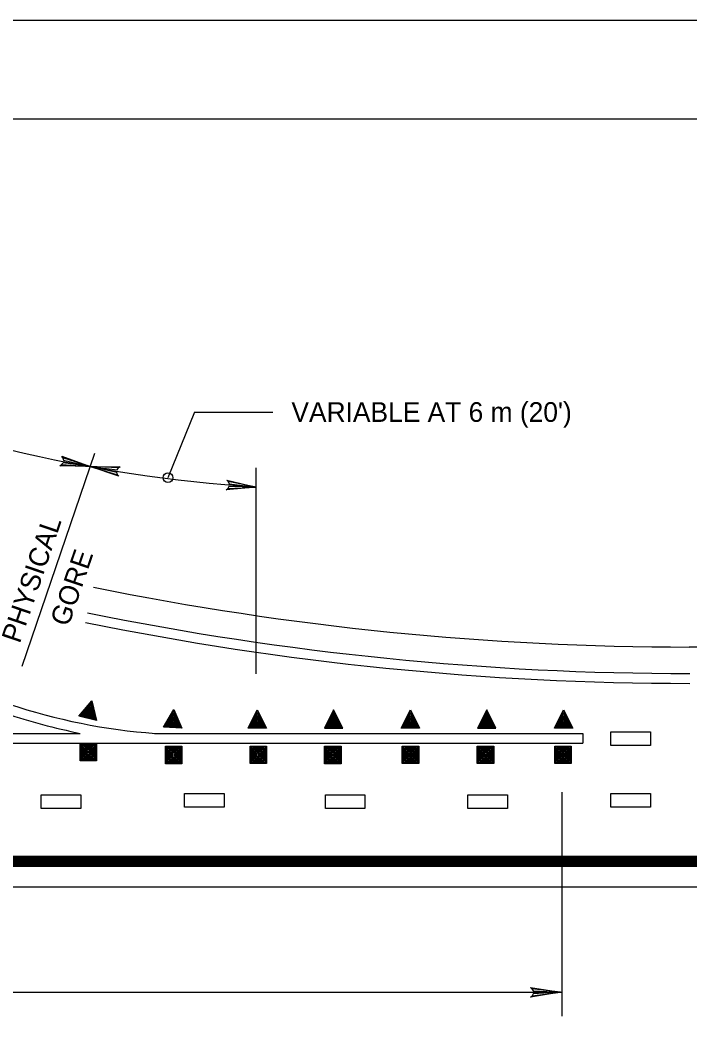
# Model space of a CAD drawing. Extents: x 639362 to 641108, y 298458 to 299646.
# Drawn here: x 639652.3 to 639754.2, y 299491.1 to 299645.6 of the extents above; entities that cross this region are included whole.
import ezdxf

# ---------------------------------------------------------------- set-up
doc = ezdxf.new("R2010")
doc.units = 0
for name, color, linetype in [('1', 7, 'Continuous'), ('2', 7, 'Continuous'), ('PLT-BNDY', 7, 'Continuous')]:
    doc.layers.add(name, color=color, linetype=linetype)

msp = doc.modelspace()

# ---------------------------------------------------------------- linework, layer by layer
at = {"layer": '1'}
msp.add_line((639402.31, 299630.63), (640188.31, 299630.63), dxfattribs=at)
at = {"layer": '2'}
for p, q in [((639678.76, 299585.99), (639674.74, 299576)), ((639678.76, 299585.99), (639690.69, 299585.99)), ((639663.56, 299579.69), (639652.5, 299547.26)), ((639688.17, 299546.13), (639688.17, 299577.52)), ((639813.29, 299550.23), (639754.09, 299550.23)), ((639661.15, 299539.71), (639663.17, 299542.06)), ((639661.33, 299539.76), (639663.12, 299541.85)), ((639661.51, 299539.82), (639663.06, 299541.63)), ((639661.69, 299539.88), (639663.01, 299541.42)), ((639661.87, 299539.93), (639662.96, 299541.2)), ((639662.96, 299541.2), (639663.32, 299539.57)), ((639663.01, 299541.42), (639663.45, 299539.44)), ((639663.06, 299541.63), (639663.58, 299539.31)), ((639663.12, 299541.85), (639663.71, 299539.17)), ((639663.17, 299542.06), (639663.84, 299539.03)), ((639663.84, 299539.03), (639661.15, 299539.71)), ((639663.71, 299539.17), (639661.33, 299539.76)), ((639663.58, 299539.31), (639661.51, 299539.82)), ((639663.45, 299539.44), (639661.69, 299539.88)), ((639663.32, 299539.57), (639661.87, 299539.93)), ((639662.05, 299540), (639662.9, 299540.99)), ((639663.19, 299539.71), (639662.05, 299540)), ((639662.23, 299540.05), (639662.85, 299540.78)), ((639663.06, 299539.84), (639662.23, 299540.05)), ((639662.41, 299540.11), (639662.79, 299540.56)), ((639662.93, 299539.98), (639662.41, 299540.11)), ((639662.58, 299540.17), (639662.74, 299540.35)), ((639662.79, 299540.11), (639662.58, 299540.17)), ((639662.74, 299540.35), (639662.79, 299540.11)), ((639662.79, 299540.56), (639662.93, 299539.98)), ((639662.85, 299540.78), (639663.06, 299539.84)), ((639662.9, 299540.99), (639663.19, 299539.71)), ((639674.08, 299538.03), (639675.61, 299540.73)), ((639674.24, 299538.12), (639675.59, 299540.5)), ((639674.41, 299538.21), (639675.58, 299540.28)), ((639674.57, 299538.3), (639675.57, 299540.06)), ((639674.74, 299538.39), (639675.56, 299539.84)), ((639674.9, 299538.48), (639675.55, 299539.62)), ((639675.55, 299539.62), (639676.08, 299538.42)), ((639675.56, 299539.84), (639676.23, 299538.31)), ((639675.57, 299540.06), (639676.39, 299538.2)), ((639675.58, 299540.28), (639676.53, 299538.09)), ((639675.59, 299540.5), (639676.69, 299537.99)), ((639675.61, 299540.73), (639676.85, 299537.88)), ((639686.95, 299537.88), (639688.34, 299540.65)), ((639687.11, 299537.98), (639688.34, 299540.43)), ((639687.27, 299538.08), (639688.34, 299540.21)), ((639687.43, 299538.18), (639688.34, 299539.99)), ((639687.59, 299538.28), (639688.34, 299539.77)), ((639687.75, 299538.38), (639688.34, 299539.55)), ((639688.34, 299540.65), (639689.73, 299537.88)), ((639688.34, 299540.43), (639689.57, 299537.98)), ((639688.34, 299540.21), (639689.41, 299538.08)), ((639688.34, 299539.99), (639689.25, 299538.18)), ((639688.34, 299539.77), (639689.09, 299538.27)), ((639688.34, 299539.55), (639688.93, 299538.37)), ((639699.96, 299540.65), (639698.57, 299537.88)), ((639699.95, 299540.43), (639698.73, 299537.98)), ((639699.96, 299540.21), (639698.89, 299538.08)), ((639699.95, 299539.99), (639699.05, 299538.18)), ((639699.95, 299539.77), (639699.21, 299538.27)), ((639699.96, 299539.55), (639699.37, 299538.37)), ((639701.18, 299537.98), (639699.95, 299540.43)), ((639700.86, 299538.18), (639699.95, 299539.99)), ((639700.7, 299538.28), (639699.95, 299539.77)), ((639701.34, 299537.88), (639699.96, 299540.65)), ((639701.02, 299538.08), (639699.96, 299540.21)), ((639700.54, 299538.38), (639699.96, 299539.55)), ((639710.26, 299537.88), (639711.65, 299540.65)), ((639710.42, 299537.98), (639711.65, 299540.43)), ((639710.58, 299538.08), (639711.65, 299540.21)), ((639710.74, 299538.18), (639711.65, 299539.99)), ((639710.9, 299538.28), (639711.66, 299539.77)), ((639711.06, 299538.38), (639711.65, 299539.55)), ((639711.65, 299540.65), (639713.04, 299537.88)), ((639711.65, 299540.43), (639712.88, 299537.98)), ((639711.65, 299540.21), (639712.72, 299538.08)), ((639711.65, 299539.99), (639712.56, 299538.18)), ((639711.65, 299539.55), (639712.24, 299538.37)), ((639711.66, 299539.77), (639712.4, 299538.27)), ((639723.27, 299540.65), (639721.88, 299537.88)), ((639723.27, 299540.43), (639722.04, 299537.98)), ((639723.27, 299540.21), (639722.2, 299538.08)), ((639723.27, 299539.99), (639722.36, 299538.18)), ((639723.26, 299539.77), (639722.52, 299538.27)), ((639723.27, 299539.55), (639722.68, 299538.37)), ((639724.01, 299538.28), (639723.26, 299539.77)), ((639724.65, 299537.88), (639723.27, 299540.65)), ((639724.49, 299537.98), (639723.27, 299540.43)), ((639724.33, 299538.08), (639723.27, 299540.21)), ((639724.17, 299538.18), (639723.27, 299539.99)), ((639723.85, 299538.38), (639723.27, 299539.55)), ((639733.57, 299537.88), (639734.96, 299540.65)), ((639733.73, 299537.98), (639734.96, 299540.43)), ((639733.9, 299538.08), (639734.96, 299540.21)), ((639734.06, 299538.18), (639734.96, 299539.99)), ((639734.22, 299538.28), (639734.97, 299539.77)), ((639734.38, 299538.38), (639734.96, 299539.55)), ((639734.96, 299540.65), (639736.35, 299537.88)), ((639734.96, 299540.43), (639736.19, 299537.98)), ((639734.96, 299540.21), (639736.03, 299538.08)), ((639734.96, 299539.99), (639735.87, 299538.18)), ((639734.96, 299539.55), (639735.55, 299538.37)), ((639734.97, 299539.77), (639735.71, 299538.27)), ((639676.85, 299537.88), (639674.08, 299538.03)), ((639676.69, 299537.99), (639674.24, 299538.12)), ((639676.53, 299538.09), (639674.41, 299538.21)), ((639676.39, 299538.2), (639674.57, 299538.3)), ((639676.23, 299538.31), (639674.74, 299538.39)), ((639676.08, 299538.42), (639674.9, 299538.48)), ((639675.06, 299538.57), (639675.54, 299539.4)), ((639675.92, 299538.53), (639675.06, 299538.57)), ((639675.22, 299538.66), (639675.53, 299539.18)), ((639675.76, 299538.63), (639675.22, 299538.66)), ((639675.39, 299538.75), (639675.51, 299538.96)), ((639675.61, 299538.74), (639675.39, 299538.75)), ((639675.51, 299538.96), (639675.61, 299538.74)), ((639675.53, 299539.18), (639675.76, 299538.63)), ((639675.54, 299539.4), (639675.92, 299538.53)), ((639689.57, 299537.98), (639687.11, 299537.98)), ((639689.41, 299538.08), (639687.27, 299538.08)), ((639689.25, 299538.18), (639687.43, 299538.18)), ((639689.09, 299538.27), (639687.59, 299538.28)), ((639688.93, 299538.37), (639687.75, 299538.38)), ((639687.91, 299538.47), (639688.34, 299539.33)), ((639688.77, 299538.47), (639687.91, 299538.47)), ((639688.07, 299538.58), (639688.34, 299539.1)), ((639688.61, 299538.57), (639688.07, 299538.58)), ((639688.23, 299538.67), (639688.34, 299538.88)), ((639688.45, 299538.67), (639688.23, 299538.67)), ((639688.34, 299539.33), (639688.77, 299538.47)), ((639688.34, 299539.1), (639688.61, 299538.57)), ((639688.34, 299538.88), (639688.45, 299538.67)), ((639698.73, 299537.98), (639701.18, 299537.98)), ((639698.89, 299538.08), (639701.02, 299538.08)), ((639699.05, 299538.18), (639700.86, 299538.18)), ((639699.21, 299538.27), (639700.7, 299538.28)), ((639699.37, 299538.37), (639700.54, 299538.38)), ((639699.95, 299539.33), (639699.53, 299538.47)), ((639699.53, 299538.47), (639700.38, 299538.47)), ((639699.96, 299539.1), (639699.69, 299538.57)), ((639699.69, 299538.57), (639700.23, 299538.58)), ((639699.96, 299538.88), (639699.85, 299538.67)), ((639699.85, 299538.67), (639700.07, 299538.67)), ((639700.38, 299538.47), (639699.95, 299539.33)), ((639700.23, 299538.58), (639699.96, 299539.1)), ((639700.07, 299538.67), (639699.96, 299538.88)), ((639712.88, 299537.98), (639710.42, 299537.98)), ((639712.72, 299538.08), (639710.58, 299538.08)), ((639712.56, 299538.18), (639710.74, 299538.18)), ((639712.4, 299538.27), (639710.9, 299538.28)), ((639712.24, 299538.37), (639711.06, 299538.38)), ((639711.22, 299538.47), (639711.65, 299539.33)), ((639712.08, 299538.47), (639711.22, 299538.47)), ((639711.38, 299538.58), (639711.65, 299539.1)), ((639711.92, 299538.57), (639711.38, 299538.58)), ((639711.54, 299538.67), (639711.65, 299538.88)), ((639711.76, 299538.67), (639711.54, 299538.67)), ((639711.65, 299539.33), (639712.08, 299538.47)), ((639711.65, 299539.1), (639711.92, 299538.57)), ((639711.65, 299538.88), (639711.76, 299538.67)), ((639722.04, 299537.98), (639724.49, 299537.98)), ((639722.2, 299538.08), (639724.33, 299538.08)), ((639722.36, 299538.18), (639724.17, 299538.18)), ((639722.52, 299538.27), (639724.01, 299538.28)), ((639722.68, 299538.37), (639723.85, 299538.38)), ((639723.27, 299539.33), (639722.84, 299538.47)), ((639722.84, 299538.47), (639723.69, 299538.47)), ((639723.27, 299539.1), (639723, 299538.57)), ((639723, 299538.57), (639723.54, 299538.58)), ((639723.27, 299538.88), (639723.16, 299538.67)), ((639723.16, 299538.67), (639723.38, 299538.67)), ((639723.69, 299538.47), (639723.27, 299539.33)), ((639723.54, 299538.58), (639723.27, 299539.1)), ((639723.38, 299538.67), (639723.27, 299538.88)), ((639736.19, 299537.98), (639733.73, 299537.98)), ((639736.03, 299538.08), (639733.9, 299538.08)), ((639735.87, 299538.18), (639734.06, 299538.18)), ((639735.71, 299538.27), (639734.22, 299538.28)), ((639735.55, 299538.37), (639734.38, 299538.38)), ((639734.54, 299538.47), (639734.96, 299539.33)), ((639735.39, 299538.47), (639734.54, 299538.47)), ((639734.69, 299538.58), (639734.96, 299539.1)), ((639735.23, 299538.57), (639734.69, 299538.58)), ((639734.85, 299538.67), (639734.96, 299538.88)), ((639735.07, 299538.67), (639734.85, 299538.67)), ((639734.96, 299539.33), (639735.39, 299538.47)), ((639734.96, 299539.1), (639735.23, 299538.57)), ((639734.96, 299538.88), (639735.07, 299538.67)), ((639512.29, 299537.09), (639661.38, 299537.09)), ((639672.69, 299537.09), (639737.89, 299537.09)), ((639689.73, 299537.88), (639686.95, 299537.88)), ((639698.57, 299537.88), (639701.34, 299537.88)), ((639713.04, 299537.88), (639710.26, 299537.88)), ((639721.88, 299537.88), (639724.65, 299537.88)), ((639736.35, 299537.88), (639733.57, 299537.88)), ((639737.89, 299537.09), (639737.89, 299535.59)), ((639742.17, 299535.25), (639742.17, 299537.32)), ((639742.18, 299537.32), (639748.19, 299537.32)), ((639748.19, 299537.32), (639748.19, 299535.25)), ((639512.29, 299535.59), (639737.89, 299535.59)), ((639661.36, 299535.58), (639663.86, 299535.58)), ((639661.36, 299532.92), (639661.36, 299535.58)), ((639661.55, 299535.44), (639663.68, 299535.44)), ((639661.55, 299533.05), (639661.55, 299535.44)), ((639661.73, 299535.27), (639663.5, 299535.27)), ((639661.73, 299533.23), (639661.73, 299535.27)), ((639661.9, 299535.09), (639663.32, 299535.09)), ((639661.9, 299533.41), (639661.9, 299535.09)), ((639662.08, 299534.91), (639663.15, 299534.91)), ((639662.08, 299533.58), (639662.08, 299534.91)), ((639663.15, 299534.91), (639663.15, 299533.58)), ((639663.32, 299535.09), (639663.32, 299533.41)), ((639663.5, 299535.27), (639663.5, 299533.23)), ((639663.68, 299535.44), (639663.68, 299533.05)), ((639663.86, 299535.58), (639663.86, 299532.92)), ((639674.36, 299535.12), (639676.86, 299535.12)), ((639674.36, 299532.47), (639674.36, 299535.12)), ((639674.55, 299534.99), (639676.68, 299534.99)), ((639674.55, 299532.59), (639674.55, 299534.99)), ((639676.68, 299534.99), (639676.68, 299532.59)), ((639676.86, 299535.12), (639676.86, 299532.47)), ((639687.26, 299535.15), (639689.76, 299535.15)), ((639687.26, 299532.5), (639687.26, 299535.15)), ((639687.44, 299535.02), (639689.57, 299535.02)), ((639687.44, 299532.62), (639687.44, 299535.02)), ((639689.57, 299535.02), (639689.57, 299532.62)), ((639689.76, 299535.15), (639689.76, 299532.5)), ((639698.59, 299535.12), (639701.08, 299535.12)), ((639698.59, 299532.47), (639698.59, 299535.12)), ((639698.77, 299534.99), (639700.9, 299534.99)), ((639698.77, 299532.59), (639698.77, 299534.99)), ((639700.9, 299534.99), (639700.9, 299532.59)), ((639701.08, 299535.12), (639701.08, 299532.47)), ((639710.41, 299535.15), (639712.91, 299535.15)), ((639710.41, 299532.5), (639710.41, 299535.15)), ((639710.6, 299535.02), (639712.73, 299535.02)), ((639710.6, 299532.62), (639710.6, 299535.02)), ((639712.73, 299535.02), (639712.73, 299532.62)), ((639712.91, 299535.15), (639712.91, 299532.5)), ((639721.83, 299535.14), (639724.33, 299535.14)), ((639721.83, 299532.49), (639721.83, 299535.14)), ((639722.01, 299535.01), (639724.14, 299535.01)), ((639722.01, 299532.61), (639722.01, 299535.01)), ((639724.14, 299535.01), (639724.14, 299532.61)), ((639724.33, 299535.14), (639724.33, 299532.49)), ((639733.62, 299535.15), (639736.12, 299535.15)), ((639733.62, 299532.5), (639733.62, 299535.15)), ((639733.81, 299535.02), (639735.93, 299535.02)), ((639733.81, 299532.62), (639733.81, 299535.02)), ((639735.93, 299535.02), (639735.93, 299532.62)), ((639736.12, 299535.15), (639736.12, 299532.5)), ((639748.19, 299535.25), (639742.18, 299535.25)), ((639663.32, 299533.41), (639661.9, 299533.41)), ((639663.15, 299533.58), (639662.08, 299533.58)), ((639662.26, 299533.76), (639662.26, 299534.74)), ((639662.26, 299534.74), (639662.97, 299534.74)), ((639662.97, 299533.76), (639662.26, 299533.76)), ((639662.44, 299534.56), (639662.79, 299534.56)), ((639662.44, 299533.94), (639662.44, 299534.56)), ((639662.79, 299533.94), (639662.44, 299533.94)), ((639662.61, 299534.38), (639662.61, 299534.11)), ((639662.79, 299534.56), (639662.79, 299533.94)), ((639662.97, 299534.74), (639662.97, 299533.76)), ((639674.73, 299534.81), (639676.5, 299534.81)), ((639674.73, 299532.77), (639674.73, 299534.81)), ((639674.9, 299534.63), (639676.32, 299534.63)), ((639674.9, 299532.95), (639674.9, 299534.63)), ((639675.08, 299534.46), (639676.15, 299534.46)), ((639675.08, 299533.13), (639675.08, 299534.46)), ((639675.26, 299533.3), (639675.26, 299534.28)), ((639675.26, 299534.28), (639675.97, 299534.28)), ((639675.44, 299534.1), (639675.79, 299534.1)), ((639675.44, 299533.48), (639675.44, 299534.1)), ((639675.79, 299533.48), (639675.44, 299533.48)), ((639675.61, 299533.92), (639675.61, 299533.66)), ((639675.79, 299534.1), (639675.79, 299533.48)), ((639675.97, 299534.28), (639675.97, 299533.3)), ((639676.15, 299534.46), (639676.15, 299533.13)), ((639676.32, 299534.63), (639676.32, 299532.95)), ((639676.5, 299534.81), (639676.5, 299532.77)), ((639687.62, 299534.84), (639689.4, 299534.84)), ((639687.62, 299532.8), (639687.62, 299534.84)), ((639687.8, 299534.66), (639689.22, 299534.66)), ((639687.8, 299532.98), (639687.8, 299534.66)), ((639687.98, 299534.48), (639689.04, 299534.48)), ((639687.98, 299533.16), (639687.98, 299534.48)), ((639688.16, 299533.33), (639688.16, 299534.31)), ((639688.16, 299534.31), (639688.87, 299534.31)), ((639688.87, 299533.33), (639688.16, 299533.33)), ((639688.33, 299534.13), (639688.69, 299534.13)), ((639688.33, 299533.51), (639688.33, 299534.13)), ((639688.69, 299533.51), (639688.33, 299533.51)), ((639688.51, 299533.95), (639688.51, 299533.69)), ((639688.69, 299534.13), (639688.69, 299533.51)), ((639688.87, 299534.31), (639688.87, 299533.33)), ((639689.04, 299534.48), (639689.04, 299533.16)), ((639689.22, 299534.66), (639689.22, 299532.98)), ((639689.4, 299534.84), (639689.4, 299532.8)), ((639698.95, 299534.81), (639700.72, 299534.81)), ((639698.95, 299532.77), (639698.95, 299534.81)), ((639699.13, 299534.63), (639700.55, 299534.63)), ((639699.13, 299532.95), (639699.13, 299534.63)), ((639699.3, 299534.46), (639700.37, 299534.46)), ((639699.3, 299533.13), (639699.3, 299534.46)), ((639699.48, 299533.3), (639699.48, 299534.28)), ((639699.48, 299534.28), (639700.19, 299534.28)), ((639699.66, 299534.1), (639700.01, 299534.1)), ((639699.66, 299533.48), (639699.66, 299534.1)), ((639700.01, 299533.48), (639699.66, 299533.48)), ((639699.84, 299533.92), (639699.84, 299533.66)), ((639700.01, 299534.1), (639700.01, 299533.48)), ((639700.19, 299534.28), (639700.19, 299533.3)), ((639700.37, 299534.46), (639700.37, 299533.13)), ((639700.55, 299534.63), (639700.55, 299532.95)), ((639700.72, 299534.81), (639700.72, 299532.77)), ((639710.78, 299534.84), (639712.55, 299534.84)), ((639710.78, 299532.8), (639710.78, 299534.84)), ((639710.95, 299534.66), (639712.37, 299534.66)), ((639710.95, 299532.98), (639710.95, 299534.66)), ((639711.13, 299534.49), (639712.2, 299534.49)), ((639711.13, 299533.16), (639711.13, 299534.49)), ((639711.31, 299533.33), (639711.31, 299534.31)), ((639711.31, 299534.31), (639712.02, 299534.31)), ((639712.02, 299533.33), (639711.31, 299533.33)), ((639711.49, 299534.13), (639711.84, 299534.13)), ((639711.49, 299533.51), (639711.49, 299534.13)), ((639711.84, 299533.51), (639711.49, 299533.51)), ((639711.66, 299533.95), (639711.66, 299533.69)), ((639711.84, 299534.13), (639711.84, 299533.51)), ((639712.02, 299534.31), (639712.02, 299533.33)), ((639712.2, 299534.49), (639712.2, 299533.16)), ((639712.37, 299534.66), (639712.37, 299532.98)), ((639712.55, 299534.84), (639712.55, 299532.8)), ((639722.19, 299534.83), (639723.97, 299534.83)), ((639722.19, 299532.79), (639722.19, 299534.83)), ((639722.37, 299534.65), (639723.79, 299534.65)), ((639722.37, 299532.97), (639722.37, 299534.65)), ((639722.55, 299534.47), (639723.61, 299534.47)), ((639722.55, 299533.15), (639722.55, 299534.47)), ((639722.72, 299533.32), (639722.72, 299534.3)), ((639722.72, 299534.3), (639723.43, 299534.3)), ((639723.43, 299533.32), (639722.72, 299533.32)), ((639722.9, 299534.12), (639723.26, 299534.12)), ((639722.9, 299533.5), (639722.9, 299534.12)), ((639723.26, 299533.5), (639722.9, 299533.5)), ((639723.08, 299533.94), (639723.08, 299533.68)), ((639723.26, 299534.12), (639723.26, 299533.5)), ((639723.43, 299534.3), (639723.43, 299533.32)), ((639723.61, 299534.47), (639723.61, 299533.15)), ((639723.79, 299534.65), (639723.79, 299532.97)), ((639723.97, 299534.83), (639723.97, 299532.79)), ((639733.98, 299534.84), (639735.76, 299534.84)), ((639733.98, 299532.8), (639733.98, 299534.84)), ((639734.16, 299534.66), (639735.58, 299534.66)), ((639734.16, 299532.98), (639734.16, 299534.66)), ((639734.34, 299534.48), (639735.4, 299534.48)), ((639734.34, 299533.16), (639734.34, 299534.48)), ((639734.52, 299533.33), (639734.52, 299534.31)), ((639734.52, 299534.31), (639735.23, 299534.31)), ((639735.23, 299533.33), (639734.52, 299533.33)), ((639734.69, 299534.13), (639735.05, 299534.13)), ((639734.69, 299533.51), (639734.69, 299534.13)), ((639735.05, 299533.51), (639734.69, 299533.51)), ((639734.87, 299533.95), (639734.87, 299533.69)), ((639735.05, 299534.13), (639735.05, 299533.51)), ((639735.23, 299534.31), (639735.23, 299533.33)), ((639735.4, 299534.48), (639735.4, 299533.16)), ((639735.58, 299534.66), (639735.58, 299532.98)), ((639735.76, 299534.84), (639735.76, 299532.8)), ((639663.86, 299532.92), (639661.36, 299532.92)), ((639663.68, 299533.05), (639661.55, 299533.05)), ((639663.5, 299533.23), (639661.73, 299533.23)), ((639676.86, 299532.47), (639674.36, 299532.47)), ((639676.68, 299532.59), (639674.55, 299532.59)), ((639676.5, 299532.77), (639674.73, 299532.77)), ((639676.32, 299532.95), (639674.9, 299532.95)), ((639676.15, 299533.13), (639675.08, 299533.13)), ((639675.97, 299533.3), (639675.26, 299533.3)), ((639689.76, 299532.5), (639687.26, 299532.5)), ((639689.57, 299532.62), (639687.44, 299532.62)), ((639689.4, 299532.8), (639687.62, 299532.8)), ((639689.22, 299532.98), (639687.8, 299532.98)), ((639689.04, 299533.16), (639687.98, 299533.16)), ((639701.08, 299532.47), (639698.59, 299532.47)), ((639700.9, 299532.59), (639698.77, 299532.59)), ((639700.72, 299532.77), (639698.95, 299532.77)), ((639700.55, 299532.95), (639699.13, 299532.95)), ((639700.37, 299533.13), (639699.3, 299533.13)), ((639700.19, 299533.3), (639699.48, 299533.3)), ((639712.91, 299532.5), (639710.41, 299532.5)), ((639712.73, 299532.62), (639710.6, 299532.62)), ((639712.55, 299532.8), (639710.78, 299532.8)), ((639712.37, 299532.98), (639710.95, 299532.98)), ((639712.2, 299533.16), (639711.13, 299533.16)), ((639724.33, 299532.49), (639721.83, 299532.49)), ((639724.14, 299532.61), (639722.01, 299532.61)), ((639723.97, 299532.79), (639722.19, 299532.79)), ((639723.79, 299532.97), (639722.37, 299532.97)), ((639723.61, 299533.15), (639722.55, 299533.15)), ((639736.12, 299532.5), (639733.62, 299532.5)), ((639735.93, 299532.62), (639733.81, 299532.62)), ((639735.76, 299532.8), (639733.98, 299532.8)), ((639735.58, 299532.98), (639734.16, 299532.98)), ((639735.4, 299533.16), (639734.34, 299533.16)), ((639655.45, 299525.67), (639655.45, 299527.74)), ((639655.45, 299527.74), (639661.46, 299527.74)), ((639661.46, 299527.74), (639661.46, 299525.67)), ((639677.26, 299525.86), (639677.26, 299527.93)), ((639677.26, 299527.93), (639683.27, 299527.93)), ((639683.27, 299527.93), (639683.27, 299525.86)), ((639698.71, 299525.67), (639698.71, 299527.74)), ((639698.71, 299527.74), (639704.72, 299527.74)), ((639704.72, 299527.74), (639704.72, 299525.67)), ((639720.41, 299525.67), (639720.41, 299527.74)), ((639720.41, 299527.74), (639726.42, 299527.74)), ((639726.42, 299527.74), (639726.42, 299525.67)), ((639734.72, 299528.16), (639734.72, 299494.02)), ((639742.17, 299525.86), (639742.17, 299527.93)), ((639742.17, 299527.93), (639748.19, 299527.93)), ((639748.19, 299527.93), (639748.19, 299525.86)), ((639661.46, 299525.67), (639655.45, 299525.67)), ((639683.27, 299525.86), (639677.26, 299525.86)), ((639704.72, 299525.67), (639698.71, 299525.67)), ((639726.42, 299525.67), (639720.41, 299525.67)), ((639748.19, 299525.86), (639742.17, 299525.86)), ((639512.29, 299518.38), (639813.29, 299518.38)), ((639512.29, 299518.23), (639813.29, 299518.23)), ((639512.29, 299518.08), (639813.29, 299518.08)), ((639512.29, 299517.93), (639813.29, 299517.93)), ((639512.29, 299517.78), (639813.29, 299517.78)), ((639512.29, 299517.63), (639813.29, 299517.63)), ((639512.29, 299517.48), (639813.29, 299517.48)), ((639512.29, 299517.33), (639813.29, 299517.33)), ((639512.29, 299517.18), (639813.29, 299517.18)), ((639512.29, 299517.03), (639813.29, 299517.03)), ((639512.29, 299516.88), (639813.29, 299516.88)), ((639512.29, 299513.74), (639813.29, 299513.74)), ((639531.37, 299497.67), (639734.72, 299497.67))]:
    msp.add_line(p, q, dxfattribs=at)
for points in [[(639658.74, 299579.03), (639658.84, 299578.69), (639662.88, 299577.69), (639658.74, 299579.03), (639658.56, 299579.26), (639662.88, 299577.69), (639658.76, 299578.26), (639658.55, 299577.99), (639662.88, 299577.69), (639658.28, 299577.83), (639658.55, 299577.99)], [(639667.06, 299576.46), (639666.94, 299576.79), (639662.88, 299577.7), (639667.06, 299576.46), (639667.24, 299576.23), (639662.88, 299577.7), (639667.02, 299577.22), (639667.22, 299577.5), (639662.88, 299577.7), (639667.48, 299577.67), (639667.22, 299577.5)], [(639683.9, 299575.41), (639684.04, 299575.08), (639688.17, 299574.58), (639683.9, 299575.41), (639683.69, 299575.61), (639688.17, 299574.58), (639684.02, 299574.65), (639683.84, 299574.35), (639688.17, 299574.58), (639683.59, 299574.16), (639683.84, 299574.35)], [(639730.15, 299498.21), (639730.31, 299497.89), (639734.47, 299497.67), (639730.15, 299498.21), (639729.93, 299498.39), (639734.47, 299497.67), (639730.32, 299497.46), (639730.17, 299497.15), (639734.47, 299497.67), (639729.93, 299496.94), (639730.17, 299497.15)]]:
    msp.add_lwpolyline(points, dxfattribs=at)
msp.add_circle((639674.74, 299576), 0.75, dxfattribs=at)
for centre, radius, start, end in [((639703.35, 299802.11), 228.03, 247.0247, 266.1831), ((639754.09, 300005.93), 455.7, 258.5199, 270), ((639754.16, 300005.2), 459, 258.4765, 270), ((639754.16, 300005.2), 460.5, 258.4765, 270), ((639679.6, 299628.88), 92.05, 251.5767, 265.7693), ((639680.87, 299632.65), 97.53, 251.5563, 258.4732)]:
    msp.add_arc(centre, radius, start, end, dxfattribs=at)
at = {"layer": 'PLT-BNDY'}
msp.add_lwpolyline([(639362.31, 299645.63), (640203.31, 299645.63), (640203.31, 299051.63), (639362.31, 299051.63)], close=True, dxfattribs=at)

# ---------------------------------------------------------------- texts
at = {"layer": '2'}
msp.add_text("VARIABLE AT 6 m (20')", height=3, dxfattribs=at).set_placement((639693.53, 299584.5))
for s, p in [('PHYSICAL', (639652.17, 299550.66)), ('GORE', (639659.59, 299553.21))]:
    msp.add_text(s, height=3, rotation=71.1572, dxfattribs=at).set_placement(p)

doc.saveas('drawing.dxf')
